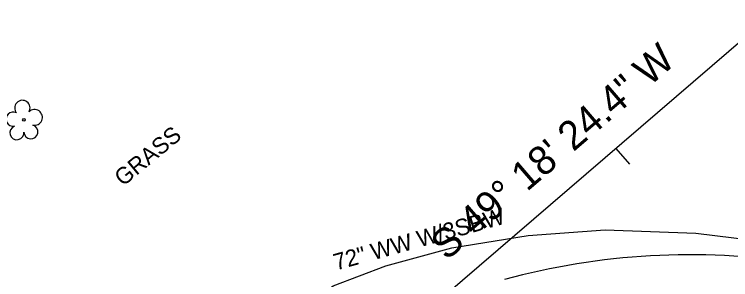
# Model space of a CAD drawing. Extents: x 1435573 to 1437263, y 981340 to 982884.
# Drawn here: x 1436162.6 to 1436335.7, y 982485.9 to 982550 of the extents above; entities that cross this region are included whole.
import ezdxf

# ---------------------------------------------------------------- set-up
doc = ezdxf.new("R2010")
doc.units = 0
for name, color, linetype in [('Exist Horizontal Baseline Alignment', 7, 'Continuous'), ('Exist Horizontal Baseline Alignment Direction Label', 7, 'Continuous'), ('Exist Horizontal Baseline Alignment Tick small', 7, 'Continuous'), ('Exist Other Culture Fence Line', 7, 'Continuous'), ('Exist Other Culture Fence Line Text', 7, 'Continuous'), ('Exist Right of Way Line', 7, 'Continuous'), ('Exist Vegetation Shrub Text', 7, 'Continuous'), ('Exist Vegetation Tree CELL', 7, 'Continuous')]:
    doc.layers.add(name, color=color, linetype=linetype)

msp = doc.modelspace()

# ---------------------------------------------------------------- linework, layer by layer
at = {"layer": 'Exist Horizontal Baseline Alignment'}
msp.add_line((1436383.8, 982582.77), (1436220.79, 982442.59), dxfattribs=at)
at = {"layer": 'Exist Horizontal Baseline Alignment Tick small'}
msp.add_line((1436307.98, 982517.57), (1436311.24, 982513.78), dxfattribs=at)
at = {"layer": 'Exist Other Culture Fence Line'}
msp.add_lwpolyline([(1436202.59, 982431.06), (1436200.71, 982438.37), (1436203.91, 982448.34), (1436212.22, 982459.42), (1436224.76, 982473.51), (1436239.65, 982484.37), (1436252.41, 982489.18), (1436268.31, 982493.59), (1436286.76, 982496.54), (1436305.36, 982497.94), (1436327.32, 982497.14), (1436350.28, 982494.3), (1436373.21, 982490.33), (1436397.21, 982484.18), (1436408.32, 982480.68)], dxfattribs=at)
at = {"layer": 'Exist Right of Way Line'}
msp.add_arc((1436325.62, 982323.89), 168, 80.9559, 105.381, dxfattribs=at)
at = {"layer": 'Exist Vegetation Tree CELL'}
msp.add_line((1436164.98, 982524.48), (1436164.98, 982524.48), dxfattribs=at)
msp.add_circle((1436164.98, 982524.48), 0.326, dxfattribs=at)
for centre, radius, start, end in [((1436164.59, 982527.35), 1.86, 330.1651, 219.7134), ((1436162.37, 982524.64), 1.73, 62.6636, 279.3457), ((1436167.53, 982525.07), 1.9, 257.1011, 134.1999), ((1436163.28, 982521.36), 1.69, 111.5671, 6.231), ((1436166.65, 982521.58), 1.7, 181.2822, 74.56)]:
    msp.add_arc(centre, radius, start, end, dxfattribs=at)

# ---------------------------------------------------------------- texts
at = {"layer": 'Exist Horizontal Baseline Alignment Direction Label'}
msp.add_text('S 49%%d 18\' 24.4" W', height=7, rotation=40.6932, dxfattribs=at).set_placement((1436267.08, 982490.31))
at = {"layer": 'Exist Other Culture Fence Line Text'}
msp.add_text('72" WW W/3SBW', height=4, rotation=15.499, dxfattribs=at).set_placement((1436240.4, 982488.07))
at = {"layer": 'Exist Vegetation Shrub Text'}
msp.add_text('GRASS', height=4, rotation=39.5399, dxfattribs=at).set_placement((1436188.91, 982508.27))

doc.saveas('drawing.dxf')
